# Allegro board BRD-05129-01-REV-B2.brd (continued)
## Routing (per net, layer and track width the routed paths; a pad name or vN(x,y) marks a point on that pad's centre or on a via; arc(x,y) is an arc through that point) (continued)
GND1_RS485: length 2.3
  TOP w0.381: C602.2 116.23,94.62 v1(116.55,94.29) U95.6
  vias: v1(110.62,93.41) v1(110.62,92.26) v1(110.62,91.12)
GND2_RS485:
  vias: v1(110.66,84.12) v1(110.66,82.98) v1(110.66,81.83)
VCC_BATT: length 3.2
  TOP w0.305: JA1.A1 v4(16.83,41.77)
  BOTTOM w0.381: v4(16.83,41.77) 17.02,41.96 C621.1 R44.1
VCCOEN_PL_M2C: length 235.8
  TOP w0.305: JA1.A20 v4(16,53.26)
  L03_SIG w0.254: v1(70.7,15.88) 69.26,17.31 69.26,18.61 70.43,19.78 v1(70.43,21.42)
  L05_SIG w0.254: v1(39.4,36.65) 39.4,36.21 46.15,29.46 51.23,29.46 53.56,27.12 53.56,25.83 54.5,24.89 54.5,24.13 55.33,23.3 58.96,23.3 59.23,23.03 61.99,23.03 62,23.05 65.04,23.05 66.67,21.41 66.67,19.9 v1(70.7,15.88) ; v1(67.22,24.85) 67.22,22.56 68.37,21.41 70.42,21.41 v1(70.43,21.42)
  L10_SIG w0.254: v1(123.1,67.88) 123.74,68.52 123.74,69.18 121.71,71.22 109.32,71.22 107.41,73.12 95.4,73.12 93.7,74.82 79.47,74.82 78.91,75.38 66.88,75.38 64.92,73.43 60.92,73.43 60.49,73.86 57.72,73.86 57.58,73.72 56.8,73.72 56.25,74.26 45.21,74.26 44.6,74.87 38.34,74.87 36.39,76.82 36.39,81.1 35.38,82.11 34.37,82.11 v1(33.77,81.52) 29.28,81.52 27.23,79.47 27.23,62.28 v1(21.64,56.69) ; v4(16,53.26) 16.46,53.72 21.51,53.72 25.1,50.13 28.17,50.13 32.53,45.77 36.8,45.77 39,43.57 39,41.79 39.4,41.39 v1(39.4,36.65)
  BOTTOM w0.178: v1(33.77,81.52) 34.3,82.05 U3.9 ; v1(67.22,24.85) 67.22,25.27 67.35,25.4 U97.9
  BOTTOM w0.254: Q26.1 v1(70.43,21.42) ; Q27.1 v1(123.1,67.88) ; U122.5 v1(70.7,15.88)
  BOTTOM w0.381: v4(16,53.26) 16.53,53.79 20.19,53.79 21.64,55.24 v1(21.64,56.69)
VCCOEN_PS_M2C: length 61.2
  TOP w0.305: JA1.A19 v4(16.83,53.2)
  L12_SIG w0.254: v4(16.83,53.2) 16.09,53.93 12.35,53.93 12.04,54.24 10.49,54.24 10.21,53.96 9.06,53.96 8.47,53.37 6.54,53.37 v1(5.25,54.66) 5.25,56.05 6.19,56.99 8.25,56.99 8.72,57.46 9.81,57.46 10.33,57.98 10.33,63.34 10.94,63.95 10.94,78.51 14.04,81.61 24.41,81.61 24.61,81.4 v1(27.29,81.4)
  BOTTOM w0.178: v1(27.29,81.4) 26.76,81.93 U5.9
  BOTTOM w0.203: v1(5.25,54.66) 5.53,54.38 U1.12
A_RS485: length 16.3
  TOP w0.381: v1(128.51,85.64) D22.1 126.14,85.64 124.87,84.38 123.17,84.38 122.9,84.11 U95.20
  BOTTOM w0.381: D22.1 v1(128.51,85.64) 130.48,85.64 132.63,87.8 J22.1
B_RS485: length 29.5
  TOP w0.381: J21.1 131.49,86.53 130.48,87.54 D22.2 124.1,87.54 122.58,86.03 122.58,85.33 121.63,84.39 U95.19
  BOTTOM w0.381: J22.2 134.67,93.69 134.67,87.04 J21.1
BRK_CTL_CONN: length 33
  TOP w0.381: 113.45,7.15 J46.1 ; J46.1 116.87,8.86 ; J46.1 116.87,7.15 ; J46.1 115.16,5.45 ; J46.1 116.87,5.45 ; J46.1 113.45,8.86 ; J46.1 113.45,5.45 ; J46.1 115.16,8.86
  BOTTOM w0.381: J46.1 116.87,7.15 ; J46.1 113.45,7.15 ; J46.1 115.16,5.45 ; J46.1 113.45,8.86 ; J46.1 116.87,5.45 ; J46.1 115.16,8.86 ; J46.1 116.87,8.86 ; J46.1 113.45,5.45
  vias: v1(113.31,11.5) v1(113.31,10.23) v1(114.58,11.5) v1(114.58,10.23) v1(115.85,11.5) v1(115.85,10.23) v1(117.12,11.5) v1(117.12,10.23)
BRK_GATE: length 2.7
  TOP w0.127: Q42.4 109.93,13.03 109.66,12.76 R678.2
BRK_GATE_S: length 2.3
  TOP w0.127: U121.5 R679.1 R678.1
CAN_CANH: length 16.8
  TOP w0.127: U94.B13 111.04,104.54 v1(110.83,104.75) ; v1(114.69,106.08) U94.A13
  L03_SIG w0.102: v1(110.83,104.75) 112.16,106.08 v1(114.69,106.08) 115.48,105.29 J20.1 117.16,105.37 J18.2
CAN_CANL: length 19.4
  TOP w0.127: v1(114.69,104.81) U94.A12 113.37,104.31 113.15,104.09 111.87,104.09 U94.B12
  L03_SIG w0.102: v1(114.69,104.81) 115.41,104.1 117.68,104.1 119.41,105.83 120.4,105.83 120.93,105.29 J19.1 122.16,105.3 J18.1
CAN_EN: length 7.9
  TOP w0.127: U94.A6 v1(106.11,101) ; U94.B6 109.66,102.54 v1(110.05,102.14)
  L03_SIG w0.102: v1(106.11,101) 107.93,101 109.08,102.14 v1(110.05,102.14)
  BOTTOM w0.13: R516.2 v1(106.11,101)
CAN_INH: length 6.7
  TOP w0.127: U94.B7 109.42,102.04 109.77,101.69 109.77,100.97 108.53,99.73 U94.A7 v1(106.11,99.73)
  BOTTOM w0.13: R514.1 v1(106.11,99.73)
CAN_STB_B: length 5.9
  TOP w0.127: U94.B14 111.82,107.08 112.08,107.35 U94.A14 v1(114.69,107.35)
  BOTTOM w0.13: R515.2 114.69,107.36 v1(114.69,107.35)
CC_PL_PGOOD: length 297.6
  TOP w0.254: v1(65.93,10.92) 69.51,10.92 v1(75.18,16.58)
  L03_SIG w0.254: v1(65.93,10.92) 63.8,10.92 63.47,10.59 61.24,10.59 59.84,11.98 48.72,11.98 48.26,12.45 45.6,12.45 44.88,11.73 38.65,11.73 34.53,15.86 19.54,15.86 19.42,15.98 15.35,15.98 14.78,15.41 11.73,15.41 v1(10.97,16.18) ; v1(75.44,88.46) 74.46,89.44 73.5,89.44 73.3,89.24 72.37,89.24 71.8,88.67 68.32,88.67 67.79,89.2 66.57,89.2 66.14,88.77 62.12,88.77 61.41,89.48 59.14,89.48 58.81,89.81 57.43,89.81 56.31,88.69 55.5,88.69 53.74,90.45 51.53,90.45 51.1,90.88 45.97,90.88 40.41,85.31 37.79,85.31 34.82,82.34 v1(34.82,81.45) ; v1(67.83,24.25) 68.1,24.52 68.94,24.52 70.61,22.86 71.17,22.86 72.01,22.02 72.01,21.18 74.32,18.87 74.32,17.44 v1(75.18,16.58)
  L05_SIG w0.254: v1(53.92,30.2) 51.89,32.23 51.89,35.02 49.02,37.89 44.76,37.89 40.13,42.52 40.13,43.05 39.59,43.59 37.5,43.59 37.12,43.97 v1(36.22,43.97) ; v1(116.66,26.23) 113.94,23.52 107.08,23.52 105.81,24.79 85.47,24.79 81.02,20.34 78.66,20.34 77.72,19.4 77.72,17.5 76.8,16.58 v1(75.18,16.58)
  L10_SIG w0.254: v1(67.83,24.25) 67.83,25.85 66.82,26.86 64.32,26.86 61.63,29.54 58.8,29.54 v1(57.79,28.53) 55.58,28.53 v1(53.92,30.2) ; v1(40.43,59.53) 40.43,63.14 34.13,69.44 34.13,80.36 34.82,81.05 v1(34.82,81.45)
  L12_SIG w0.254: v1(36.22,43.97) 36.99,43.97 37.59,44.57 37.59,53.56 39.58,55.55 39.58,58.68 v1(40.43,59.53)
  BOTTOM w0.13: R28.2 v1(36.22,43.97) 36.01,43.76 U19.25 ; Q10.1 10.36,16.78 v1(10.97,16.18)
  BOTTOM w0.178: U3.8 34.99,81.62 v1(34.82,81.45) ; Q43.1 113.56,39.29 ; U97.8 68.41,24.54 68.11,24.25 v1(67.83,24.25)
  BOTTOM w0.254: U122.3 74.97,16.38 v1(75.18,16.58) ; v1(75.44,88.46) 75.65,88.26 U8.3 ; v1(116.66,26.23) 118.18,26.23 121.31,29.36 121.31,33.06 119.8,34.56 118.59,34.56 116.21,36.95 115.55,36.95 113.56,38.94 113.56,39.29 ; U9.3 58,28.74 v1(57.79,28.53)
CC_PS_PGOOD: length 183.1
  TOP w0.254: v1(29.61,43.94) 24.2,43.94 v1(20.01,39.75)
  L03_SIG w0.254: v1(29.61,43.94) 30.64,44.97 32.81,44.97 34.02,43.76 35.07,43.76 36.14,44.83 v1(36.7,44.83)
  L05_SIG w0.254: v1(6.02,22.27) 7.51,23.77 7.51,35.05 11.17,38.71 11.17,43.56 10.17,44.56 10.17,47.53 9.29,48.41 8.51,48.41 7.46,49.45 7.46,51.51 v1(6.35,52.62)
  L10_SIG w0.254: v1(65.81,75.22) 64.66,74.06 61.18,74.06 60.7,74.54 58.34,74.54 v1(56.94,75.94)
  L12_SIG w0.254: v1(56.94,75.94) 56.94,76.44 55.5,77.88 53.5,77.88 53.21,77.59 53.21,76.55 52.96,76.3 51.71,76.3 50.72,77.29 46.45,77.29 46,76.83 46,75.92 44.98,74.9 42.24,74.9 41.76,75.37 34.42,75.37 v1(27.35,82.44) 26.71,83.09 14.31,83.09 10.31,79.09 10.31,67.25 6.22,63.17 6.22,58.11 4.62,56.51 4.62,54.35 v1(6.35,52.62) ; v1(6.02,22.27) 12.44,28.7 14.75,28.7 18.94,32.89 18.94,38.68 v1(20.01,39.75)
  BOTTOM w0.13: U19.24 35.49,44.1 36.22,44.83 v1(36.7,44.83) 36.82,44.95 R7.2 ; Q8.1 5.61,21.86 v1(6.02,22.27)
  BOTTOM w0.178: U5.8 27.18,82.61 v1(27.35,82.44)
  BOTTOM w0.203: U1.14 5.57,52.89 5.84,52.62 v1(6.35,52.62)
  BOTTOM w0.254: U12.3 65.61,75.01 v1(65.81,75.22) ; U96.3 56.69,75.69 v1(56.94,75.94)
CC_PS_POR_B: length 44.1
  TOP w0.127: SW2.2 4.84,46.98 5.14,47.28 v1(9.56,47.28)
  L12_SIG w0.102: v1(9.56,47.28) 11.22,45.61 11.22,41.46 13.75,38.93 15.97,38.93 19.6,42.56 19.6,43.4 24.74,48.54 32.29,48.54 33.21,47.62 v1(35.07,47.62)
  BOTTOM w0.13: R452.1 35.08,47.61 v1(35.07,47.62)
CC_PS_POR_B_R: length 2.9
  BOTTOM w0.13: U19.23 35.09,44.28 35.18,44.37 35.18,44.77 35.09,44.86 35.09,45.47 R452.2 C548.1
DC_LINK: length 117.9
  TOP w0.381: C751.1 94.69,23.33 ; C751.1 93.62,22.27 ; C751.1 93.62,21.2 ; C751.1 95.75,23.33 ; C751.1 94.69,21.2 ; C751.1 93.62,23.33 ; C751.1 95.75,22.27 ; C751.1 95.75,21.2 ; 125.16,5.45 J46.3 ; J46.3 126.42,8.41 ; J46.3 126.87,7.15 ; J46.3 123.9,8.41 ; J46.3 126.42,5.9 ; J46.3 125.16,8.86 ; J46.3 123.9,5.9 ; v1(110.98,25.29) 110.98,23.9 R659.2
  L03_SIG w0.381: J46.3 126.42,8.41 ; J46.3 126.42,5.9 ; J46.3 123.9,8.41 ; J46.3 126.87,7.15 ; J46.3 125.16,8.86 ; J46.3 125.16,5.45 ; J46.3 123.9,5.9 ; J46.3 123.45,7.15 ; 93.88,21.46 C751.1 ; C751.1 95.75,22.27 ; C751.1 93.62,22.27 ; C751.1 95.49,23.07 ; C751.1 94.69,21.2 ; C751.1 94.69,23.33 ; C751.1 93.88,23.07 ; C751.1 95.49,21.46
  L07_PWR w0.381: 94.69,21.07 C751.1 ; C751.1 95.58,21.37 ; C751.1 94.69,23.46 ; C751.1 93.79,23.16 ; C751.1 93.49,22.27 ; C751.1 95.88,22.27 ; C751.1 93.79,21.37 ; C751.1 95.58,23.16 ; 125.16,5.32 J46.3 ; J46.3 126.51,5.81 ; J46.3 126.51,8.5 ; J46.3 123.81,8.5 ; J46.3 123.32,7.15 ; J46.3 126.99,7.15 ; J46.3 125.16,8.99 ; J46.3 123.81,5.81
  BOTTOM w0.381: C751.1 95.75,23.33 ; C751.1 93.62,23.33 ; C751.1 93.62,22.27 ; C751.1 95.75,22.27 ; C751.1 94.69,21.2 ; C751.1 94.69,23.33 ; C751.1 93.62,21.2 ; C751.1 95.75,21.2 ; 123.9,8.41 J46.3 ; J46.3 126.42,8.41 ; J46.3 123.45,7.15 ; J46.3 126.87,7.15 ; J46.3 125.16,8.86 ; J46.3 126.42,5.9 ; J46.3 123.9,5.9 ; J46.3 125.16,5.45 ; R660.1 114.42,44.96 114.42,45.72 113.61,46.53 v1(106.09,46.53) ; R762.1 R761.1 111.23,31.99 ; v1(110.98,25.29) U113.1 ; R531.1 130.48,13.31 v1(130.27,13.1)
  vias: v1(95.93,27.86) v1(95.93,26.59) v1(97.2,27.86) v1(97.2,26.59) v1(97.71,62.53) v1(97.71,61.26) v1(97.71,59.99) v1(97.71,56.18) v1(97.71,49.83) v1(97.71,48.56) v1(97.71,46.02) v1(97.71,44.75) v1(97.71,43.48) v1(97.71,39.67) v1(97.71,34.59) v1(97.71,33.32) v1(97.71,32.05) v1(97.71,30.78) v1(97.71,29.51) v1(98.47,27.86) v1(98.47,26.59) v1(99.74,29.13) v1(99.74,27.86) v1(99.74,26.59) v1(101.01,29.13) v1(101.01,27.86) v1(101.01,26.59) v1(102.28,64.82) v1(102.28,63.55) v1(102.28,62.28) v1(102.28,47.8) v1(102.28,46.53) v1(102.28,45.26) v1(102.28,29.13) v1(102.28,27.86) v1(102.28,26.59) v1(103.55,64.82) v1(103.55,63.55) v1(103.55,62.28) v1(103.55,47.8) v1(103.55,46.53) v1(103.55,45.26) v1(103.55,29.13) v1(103.55,27.86) v1(103.55,26.59) v1(104.82,63.55) v1(104.82,62.28) v1(104.82,46.53) v1(104.82,45.26) v1(104.82,29.13) v1(104.82,27.86) v1(104.82,26.59) v1(106.09,64.82) v1(106.09,63.55) v1(106.09,62.28) v1(106.09,47.8) v1(106.09,45.26) v1(106.09,29.13) v1(106.09,27.86) v1(106.09,26.59) v1(107.36,27.86) v1(107.36,26.59) v1(108.63,27.86) v1(108.63,26.59) v1(114.25,31.34) v1(114.25,30.07) v1(129,16.91) v1(129,15.64) v1(129,14.37) v1(129,13.1) v1(129,11.83) v1(130.27,16.91) v1(130.27,15.64) v1(130.27,14.37) v1(130.27,11.83)
DCLINK_CONN: length 46.5
  TOP w0.635: J39.1 127.83,21.85 ; J39.1 123.01,26.67 ; J39.1 125.42,21.85 ; J39.1 125.42,26.67 ; J39.1 123.01,21.85 ; J39.1 123.01,24.26 ; J39.1 127.83,24.26 ; J39.1 127.83,26.67
  BOTTOM w0.635: J39.1 127.83,24.26 ; J39.1 125.42,26.67 ; J39.1 123.01,26.67 ; J39.1 123.01,21.85 ; J39.1 125.42,21.85 ; J39.1 123.01,24.26 ; J39.1 127.83,26.67 ; J39.1 127.83,21.85
  vias: v1(122.55,26.81) v1(122.55,25.54) v1(122.55,24.4) v1(122.55,23.26) v1(122.55,22.12) v1(122.55,20.85)
DCLINK_CRNT: length 42.5
  L12_SIG w0.381: v1(116.51,30.02) 116.51,33.03 115.29,34.26 110.99,34.26 110.36,34.9 107.36,34.9 105.36,36.9 97.94,36.9 90.6,44.24 86.22,44.24 84.88,45.58 v1(84.88,45.79)
  BOTTOM w0.381: R663.2 116.5,29.2 C759.1 v1(116.51,30.02) ; v1(84.88,45.79) R728.1
DCLINK_CS_B: length 9.7
  L12_SIG w0.102: v1(55.67,35.04) 54.78,35.92 v1(54.78,40.43)
  BOTTOM w0.13: v1(55.67,35.04) 56.94,35.04 57.18,34.79 U114.10 ; U115.7 53.56,41.11 54.11,41.11 v1(54.78,40.43)
DCLINK_CURRENT+: length 2.6
  TOP w0.381: C825.1 v1(64.88,33.65)
  BOTTOM w0.254: v1(64.88,33.65) 64.39,34.14 U114.8
  BOTTOM w0.381: C825.1 v1(64.88,33.65)
DCLINK_CURRENT-: length 2.4
  TOP w0.381: C824.1 v1(64.88,34.79)
  BOTTOM w0.254: U114.7 v1(64.88,34.79)
  BOTTOM w0.381: C824.1 v1(64.88,34.79)
DCLINK_DATAA: length 7
  BOTTOM w0.13: U114.14 55.16,37.39 54.15,38.4 54.15,40.43 53.89,40.7 U115.8
DCLINK_DATAB: length 9.9
  L12_SIG w0.102: v1(53.47,39.67) 53.47,40.44 54.07,41.04 55.13,41.04 55.56,40.61 55.56,37.96 v1(56.78,36.74)
  BOTTOM w0.13: U114.13 v1(56.78,36.74) ; v1(53.47,39.67) 52.97,40.18 U115.9
DCLINK_INPUT: length 3.4
  TOP w0.381: R659.1 113.58,23.71 v1(113.58,25.29)
  BOTTOM w0.381: v1(113.58,25.29) U113.8
  vias: v1(113.36,19.58) v1(113.36,18.44) v1(114.5,19.58) v1(114.5,18.44) v1(115.9,19.58) v1(115.9,18.44) v1(117.04,18.44)
DCLINK_SCLK: length 7.4
  BOTTOM w0.13: U114.15 57.22,38.04 56.94,37.77 56.18,37.77 55.42,38.53 55.42,40.81 54.77,41.47 53.58,41.47 U115.6
DCLINK_VOCM: length 19.1
  L10_SIG w0.381: v1(69.96,39.33) v1(71.11,39.33) 71.17,39.39 74.89,39.39 v1(76.11,40.61) 77.19,41.69 81.45,41.69 81.81,42.06 82.6,42.06 v1(83.42,41.24)
  BOTTOM w0.254: v1(83.42,41.24) 83.48,41.3 U134.2 ; U133.2 76.24,40.74 v1(76.11,40.61)
  BOTTOM w0.381: U137.7 70.88,39.56 v1(71.11,39.33) ; U137.6 70.23,39.59 v1(69.96,39.33)
DCLINK_VOCM2: length 18
  L10_SIG w0.381: v1(84.88,41.38) 84.88,40.84 84.02,39.98 78.2,39.98 v1(77.64,40.53) 73.83,36.72 72.28,36.72 v1(72.26,36.7) 72.23,36.72 71.27,36.72 v1(71.24,36.7)
  BOTTOM w0.381: v1(84.88,41.38) R727.1 ; v1(77.64,40.53) R723.1
DCLINK_VOLT: length 53.9
  L10_SIG w0.381: v1(120.98,45.03) 119.53,43.58 117.85,43.58 116,41.73 116,40.31 114.98,39.29 100.5,39.29 97.53,42.26 92.58,42.26 90.59,44.26 86.19,44.26 85.67,44.78 82.85,44.78 82.6,45.02 v1(77.64,45.02)
  BOTTOM w0.381: v1(120.98,45.03) 120.66,44.72 120.66,43.03 120.37,42.74 U135.7 U135.6 ; v1(77.64,45.02) R724.1
DCLINK_VOLTAGE+: length 2.6
  TOP w0.381: C823.1 v1(64.88,39.19)
  BOTTOM w0.254: v1(64.88,39.19) 64.39,38.69 U114.1
  BOTTOM w0.381: C823.1 v1(64.88,39.19)
DCLINK_VOLTAGE-: length 2.4
  TOP w0.381: C822.1 v1(64.88,38.04)
  BOTTOM w0.254: U114.2 v1(64.88,38.04)
  BOTTOM w0.381: C822.1 v1(64.88,38.04)
EEPROM_WC_B: length 44.2
  TOP w0.127: v1(34.64,28.42) 34.5,28.28 R256.1
  L10_SIG w0.102: v1(63.8,18.52) 62.77,19.55 60.68,19.55 59.97,20.26 58.06,20.26 57.61,20.72 54.32,20.72 53.13,19.53 53.13,18.35 52.25,17.47 50.54,17.47 47.5,20.5 38.8,20.5 35.18,24.13 35.18,25.95 34.5,26.63 34.5,28.27 v1(34.64,28.42)
  BOTTOM w0.13: v1(34.64,28.42) 34.5,28.27 U15.7 ; v1(63.8,18.52) 63.8,21.23 Q19.3
FB_UTIL_3V3: length 3.4
  BOTTOM w0.254: U7.4 6.06,41.61 5.86,41.42 R38.1
  BOTTOM w0.457: R38.1 C41.2 R39.2
FTDI_3V3_FB: length 4.4
  BOTTOM w0.254: U11.4 39.78,15.72 39.72,15.79 38.99,15.79 38.79,15.59 R41.1
  BOTTOM w0.381: R41.1 38.05,15.59 R36.2 38.05,13.57 C44.2
FTDI_3V3_PG: length 3.3
  TOP w0.381: R40.2 41.19,16.44 40.47,15.72 39.93,15.72 v1(39.44,15.22)
  BOTTOM w0.229: U11.3 v1(39.44,15.22)
FTDI_EEPROM_WC: length 3.2
  BOTTOM w0.13: U24.52 62.29,19.96 62.29,19.96 R262.1 62.74,20.32 63.07,20.66 Q19.1
FTDI_LS_OE_B: length 5.3
  TOP w0.127: v1(53.1,16.46) 53.11,16.47 R235.2 53.75,17.43 Q13.1
  BOTTOM w0.13: U24.22 v1(53.1,16.46)
FTDI_PS_POR_B: length 41.9
  TOP w0.13: R266.2 v1(40.97,17.54)
  L03_SIG w0.102: v1(50.95,16.96) 49.7,18.21 49.7,20.75 48.32,22.13 48.32,25.59 47.11,26.79 47.11,27.55 43.71,30.96 40.07,30.96 39.69,31.33 38.72,31.33 38.34,30.95 35.35,30.95 33.78,29.38 v1(33.41,29.38)
  L10_SIG w0.102: v1(40.97,17.54) 41.59,16.92 46.1,16.92 46.26,17.07 47.42,17.07 47.54,16.96 v1(50.95,16.96)
  BOTTOM w0.13: Q46.1 40.93,17.58 v1(40.97,17.54) ; U24.23 v1(50.95,16.96)
FTDI_PS_SRST_B: length 30.6
  TOP w0.13: R765.2 v1(48.04,17.5)
  L03_SIG w0.102: v1(32.35,29.38) 32.83,28.9 33.98,28.9 35.11,30.03 37.1,30.03 37.12,30.01 40.35,30.01 40.79,30.45 43.43,30.45 46.4,27.48 46.4,22.27 48.64,20.04 48.64,18.1 v1(48.04,17.5)
  BOTTOM w0.13: U24.24 48.09,17.46 v1(48.04,17.5) 47.91,17.5 47.75,17.67 Q48.1
FTDI_TCK: length 22.7
  L03_SIG w0.102: v1(50.08,13.13) 48.26,14.95 47.84,14.95 45.87,16.92 45.87,17.72 45.39,18.21 43.51,18.21 40.18,21.54 40.18,23.16 39.38,23.96 v1(39.38,26.67)
  BOTTOM w0.13: U24.16 51.36,12.74 50.96,13.13 v1(50.08,13.13) ; U22.6 38.79,26.98 39.1,26.67 v1(39.38,26.67)
FTDI_TDI: length 21.5
  L03_SIG w0.102: v1(38.39,26.67) 38.39,24.04 37.61,23.26 37.61,21.73 38.71,20.64 39.9,20.64 43.35,17.19 44.24,17.19 v1(47.93,13.51)
  BOTTOM w0.13: v1(47.93,13.51) 48.38,13.96 U24.17 ; U22.7 v1(38.39,26.67)
FTDI_TDO: length 14.1
  TOP w0.13: U25.9 v1(47.31,24.75)
  L05_SIG w0.102: v1(50.88,14.46) 48.85,16.49 48.85,19.4 48.24,20 48.24,23.82 v1(47.31,24.75)
  BOTTOM w0.13: U24.18 v1(50.88,14.46)
FTDI_TMS: length 15.2
  TOP w0.13: U25.8 47.97,25.15 v1(47.31,25.81)
  L05_SIG w0.102: v1(47.31,25.81) 46.83,25.33 46.83,22.92 46.94,22.81 46.94,18.7 46.46,18.23 46.46,15.93 v1(47.93,14.47)
  BOTTOM w0.13: v1(47.93,14.47) 48.41,14.96 U24.19
FTDI_UARTB_RXD: length 11.8
  L10_SIG w0.102: v1(50.96,18.96) 46.13,23.79 46.13,25.33 v1(45.37,26.08)
  BOTTOM w0.13: U64.9 v1(45.37,26.08) ; U24.27 v1(50.96,18.96)
FTDI_UARTB_TXD: length 18
  L10_SIG w0.102: v1(45.37,27.14) 50.35,27.14 51.39,26.1 51.39,21.85 51.99,21.25 v1(51.99,18.46)
  BOTTOM w0.13: U64.8 44.71,26.48 v1(45.37,27.14) ; U24.26 v1(51.99,18.46)
FWUEN_C2M_B: length 27.4
  TOP w0.127: v1(2.97,76.12) 3.09,76.25 SW1.2
  TOP w0.13: C236.1 v1(2.97,76.12) ; JA1.C28 v4(14.29,58.91)
  L03_SIG w0.102: v1(2.97,76.12) 2.97,73.86 5.66,71.17 5.66,67.38 10.11,62.94 10.11,60.27 12.69,57.68 13.64,57.68 13.89,57.93 13.89,58.52 v4(14.29,58.91)
GEM0_AVDD_3V3: length 6.3
  TOP w0.254: U98.11 66.03,94.97 v1(67.02,95.96) ; v1(60.55,95.96) 61.53,94.98 U98.20
  TOP w0.381: C625.1 C635.1 61.1,96.5 v1(60.55,95.96)
  vias: v1(68.03,95.96) v1(69.05,95.96)
GEM1_AVDD_3V3: length 8.6
  BOTTOM w0.254: v1(93.2,89.98) 93.2,89.5 93.7,89 U99.11 ; v1(100.29,90.13) 100.29,89.88 99.87,89.45 99.11,89.45 98.94,89.29 U99.20
  BOTTOM w0.381: 107.17,89.28 C660.1 106.61,89.84 ; v1(93.2,89.98) 93.2,90.11 93.01,90.3 C659.1 C649.1 ; v1(100.29,90.13) 100.29,90.87 C658.1 C648.1
  vias: v1(106.09,89.45) v1(106.09,88.31) v1(106.09,87.17)
GEM1_XTAL_IN: length 21.7
  TOP w0.13: v1(80.95,79.21) 83.1,79.21 87.73,83.84 87.73,88.62 88.46,89.35 v1(88.46,89.4)
  BOTTOM w0.13: v1(88.46,89.4) 89.18,88.69 91.41,88.69 91.77,89.05 92.32,89.05 92.61,88.77 92.61,88.59 93.29,87.9 U99.9 ; R478.2 v1(80.95,79.21)
GEM1_XTAL_IN_R: length 1.9
  BOTTOM w0.13: U91.8 78.89,79.68 79.36,79.21 R478.1
GEM2_AVDD_3V3: length 7.4
  TOP w0.254: U101.11 98.94,89.6 v1(99.44,90.09) 99.36,90.17 C680.1 C681.1 ; U101.20 94.44,89.6 v1(94.06,89.98)
  TOP w0.381: 106.69,90.85 C682.1 ; C682.1 107.17,91.34 ; C682.1 107.17,90.37 ; v1(94.06,89.98) 94.06,90.62 C670.1 C671.1
  vias: v1(105.84,92.5) v1(105.84,91.49) v1(105.84,90.47)
GEM2_XTAL_IN: length 38.5
  TOP w0.127: v1(104.95,89.84) 104.23,89.11 101.91,89.11 101.57,89.45 101.03,89.45 100.19,88.61 100.19,88.09 100,87.9 U101.9
  L12_SIG w0.102: v1(104.95,89.84) 104.48,90.31 103.52,90.31 103,89.78 101.28,89.78 100.64,89.15 100.38,89.15 99.17,87.94 99.17,85.7 98.02,84.55 95.16,84.55 93.91,85.8 92.51,85.8 92.06,86.24 91.18,86.24 89.91,84.97 88.12,84.97 83.47,80.33 v1(80.95,80.33)
  BOTTOM w0.13: R480.2 v1(80.95,80.33)
GEM2_XTAL_IN_R: length 1.7
  BOTTOM w0.13: U91.7 77.71,80.33 R480.1
GISOIN_RS485: length 4
  TOP w0.381: D22.3 v1(126.07,86.59)
  BOTTOM w0.381: D23.3 v1(125.9,99.69) ; v1(114.68,85.28) 114.92,85.52 C604.2 ; C603.2 v1(114.67,86.52)
  vias: v1(110.38,80.23) v1(111.27,79.42)
GTR_DP0_C2M_N_NC: length 0.6
  TOP w0.089: v7(16.95,76.1) JA1.A56
GTR_DP0_C2M_P_NC: length 0.6
  TOP w0.089: v7(16.02,76.1) JA1.A55
GTR_DP0_M2C_N_NC: length 0.6
  TOP w0.089: v4(15.99,77.37) JA1.B58
GTR_DP0_M2C_P_NC: length 0.6
  TOP w0.089: v4(15.06,77.37) JA1.B57
GTR_DP1_C2M_N_NC: length 0.6
  TOP w0.089: JA1.C56 v7(14.41,76.1)
GTR_DP1_C2M_P_NC: length 0.6
  TOP w0.089: JA1.C55 v7(13.48,76.1)
GTR_DP1_M2C_N_NC: length 0.6
  TOP w0.089: JA1.A48 v3(16.95,71.02)
GTR_DP1_M2C_P_NC: length 0.6
  TOP w0.089: JA1.A47 v3(16.02,71.02)
GTR_DP2_C2M_C_N: length 3.6
  BOTTOM w0.109: U43.48 64.38,87.34 64.46,87.26 64.46,85.96 64.95,85.46 64.95,85.13 C309.2
GTR_DP2_C2M_C_P: length 3.6
  BOTTOM w0.109: U43.47 64.78,87.41 64.71,87.33 64.71,86.06 65.2,85.57 65.2,85.21 C310.2
GTR_DP2_C2M_N: length 61
  TOP w0.089: JA1.B54 v3(15.99,74.83)
  L03_SIG w0.109: v1(64.68,82.12) 64.99,81.81 64.99,81.58 63.95,80.54 61.34,80.54 60.83,81.05 60.37,81.05 60.24,81.18 60.24,81.48 60.11,81.6 59.93,81.6 59.79,81.47 59.79,81.18 59.66,81.05 58.14,81.05 57.78,80.69 53.54,80.69 52.78,79.93 44.78,79.93 44.5,80.21 44.5,80.87 42.77,82.6 38.07,82.6 37.08,81.61 37.08,80.27 31.13,74.32 15.78,74.32 15.62,74.48 15.62,74.7 15.75,74.83 v3(15.99,74.83)
  BOTTOM w0.109: v1(64.68,82.12) 64.99,82.43 64.99,83.63 C309.1
GTR_DP2_C2M_P: length 61
  TOP w0.089: JA1.B53 v3(15.06,74.83)
  L03_SIG w0.109: v1(65.55,82.12) 65.24,81.81 65.24,81.48 64.05,80.29 61.24,80.29 60.73,80.79 58.24,80.79 57.89,80.44 53.64,80.44 52.88,79.68 44.67,79.68 44.24,80.1 44.24,80.76 42.66,82.34 38.17,82.34 37.34,81.51 37.34,80.16 31.23,74.06 15.67,74.06 15.36,74.37 15.36,74.65 15.18,74.83 v3(15.06,74.83)
  BOTTOM w0.109: v1(65.55,82.12) 65.24,82.43 65.24,83.63 C310.1
GTR_DP2_M2C_C_N: length 3.4
  BOTTOM w0.109: U43.51 63.18,87.41 63.21,87.38 63.21,85.17 C315.2
GTR_DP2_M2C_C_P: length 3.4
  BOTTOM w0.109: U43.50 63.58,87.41 63.46,87.29 63.46,85.17 C316.2
GTR_DP2_M2C_N: length 60.6
  TOP w0.089: JA1.D58 v3(13.45,77.37)
  L03_SIG w0.109: v1(62.9,82.12) 63.21,81.81 63.21,81.62 63.1,81.5 62.03,81.5 61.45,82.08 61.45,82.27 61.66,82.48 61.66,82.66 61.53,82.79 61.34,82.79 61.13,82.58 60.95,82.58 60.6,82.93 53.74,82.93 51.76,80.95 45.82,80.95 43.26,83.51 37.23,83.51 35.61,81.89 35.61,81.19 31.32,76.91 13.21,76.91 13.08,77.04 13.08,77.24 13.21,77.37 v3(13.45,77.37)
  BOTTOM w0.109: C315.1 62.89,83.51 63.21,83.2 63.21,82.43 v1(62.9,82.12)
GTR_DP2_M2C_P: length 60.5
  TOP w0.109: JA1.D57 v3(12.52,77.37)
  L03_SIG w0.109: v3(12.52,77.37) 12.66,77.37 12.82,77.21 12.82,76.94 13.11,76.65 31.43,76.65 35.86,81.09 35.86,81.78 37.33,83.26 43.15,83.26 45.72,80.69 51.87,80.69 53.85,82.67 60.5,82.67 61.92,81.25 63.2,81.25 63.47,81.51 63.47,81.81 v1(63.77,82.12)
  BOTTOM w0.109: C316.1 63.78,83.51 63.46,83.2 63.46,82.43 v1(63.77,82.12)
GTR_DP3_C2M_N_NC: length 0.6
  TOP w0.089: JA1.D50 v3(13.45,72.29)
GTR_DP3_C2M_P_NC: length 0.6
  TOP w0.089: JA1.D49 v3(12.52,72.29)
GTR_DP3_M2C_N_NC: length 0.6
  TOP w0.109: JA1.C52 v3(14.41,73.56)
GTR_DP3_M2C_P_NC: length 0.6
  TOP w0.109: JA1.C51 v3(13.48,73.56)
GTR_REFCLK0_C2M_N_NC: length 0.6
  TOP w0.089: JA1.C48 v4(14.41,71.02)
GTR_REFCLK0_C2M_P_NC: length 0.6
  TOP w0.089: JA1.C47 v4(13.48,71.02)
GTR_REFCLK1_C2M_N_NC: length 0.6
  TOP w0.089: JA1.B50 v4(15.99,72.29)
GTR_REFCLK1_C2M_P_NC: length 0.6
  TOP w0.089: JA1.B49 v4(15.06,72.29)
GTR_REFCLK2_C2M_N: length 15.1
  TOP w0.089: v9(13.45,74.83) JA1.D54
  BOTTOM w0.089: v9(13.45,74.83) 13.1,74.49 13.1,74.25 12.86,74.01 11.63,74.01 10.03,72.41 10.03,67.44 9.25,66.66 8.28,66.66 R495.1 7.66,66.64 6.59,66.64 6.08,66.13 U89.5
GTR_REFCLK2_C2M_P: length 15.1
  TOP w0.089: v9(12.52,74.83) JA1.D53
  BOTTOM w0.089: v9(12.52,74.83) 12.85,74.51 12.85,74.36 12.75,74.27 11.53,74.27 11.28,74.01 11.1,74.01 11.02,74.09 10.87,74.09 10.77,73.99 10.77,73.84 10.86,73.75 10.86,73.6 9.78,72.51 9.78,67.55 9.15,66.92 8.28,66.92 R495.2 7.61,66.89 6.62,66.89 6.11,67.4 U89.4
GTR_REFCLK3_C2M_N_NC: length 0.6
  TOP w0.094: JA1.A52 v7(16.95,73.56)
GTR_REFCLK3_C2M_P_NC: length 0.6
  TOP w0.094: JA1.A51 v7(16.02,73.56)
HDA00_CC: length 90.9
  TOP w0.13: JA1.D16 v4(12.65,50.75)
  L05_SIG w0.102: v1(70.3,13.38) 70.3,13.97 69.16,15.11 67.82,15.11 65.62,17.3 65.62,18.69 64.53,19.78 59.56,19.78 58.9,20.44 56.38,20.44 54.09,22.74 53.3,22.74 52.55,23.49 52.55,26.46 50.62,28.39 45.68,28.39 39.48,34.59 37.59,34.59 v1(36.67,35.5)
  L10_SIG w0.102: v1(36.67,35.5) 37.16,35.99 37.16,38.78 35.96,39.98 33.32,39.98 31.53,41.76 28.69,41.76 24.3,46.15 24.3,48.33 20.09,52.55 17.99,52.55 17.44,51.99 13.33,51.99 13.09,51.75 13.09,51.2 v4(12.65,50.75)
  BOTTOM w0.13: J47.2 71.11,10.02 D21.1 R680.2 69.92,13 v1(70.3,13.38)
HDA01_NC: length 0.4
  TOP w0.13: JA1.D17 v4(12.65,51.38)
HDA02: length 123.3
  TOP w0.13: JA1.D18 v4(13.47,52.59)
  L05_SIG w0.102: v4(13.47,52.59) 13.89,53.01 13.89,53.51 14.1,53.73 17.35,53.73 18.25,52.83 33.36,52.83 34.11,52.08 41,52.08 42.02,51.06 45.76,51.06 46.04,51.34 48.44,51.34 50.74,53.63 52.06,53.63 53.97,55.54 53.97,64.29 54.74,65.06 64.96,65.06 66.08,63.94 66.08,59.67 65.88,59.48 65.88,56.06 67,54.94 67.66,54.94 68.05,54.55 74.16,54.55 74.54,54.93 77.65,54.93 78.02,54.55 81.43,54.55 82.12,53.86 85.46,53.86 85.7,54.1 87.42,54.1 89.73,51.79 93.04,51.79 97.13,47.7 99.51,47.7 101.37,45.84 106.42,45.84 106.85,45.41 v1(106.85,43.17)
  BOTTOM w0.13: R618.1 v1(106.85,43.17)
HDA03: length 121.8
  TOP w0.13: JA1.B16 v4(15.19,50.75)
  L05_SIG w0.102: v1(106.85,60.06) 106.85,60.63 107.34,61.11 107.34,65.43 106.55,66.21 98.57,66.21 97.48,65.12 90.34,65.12 87.6,67.86 87.04,67.86 84.86,70.05 77.87,70.05 77.62,69.79 74.62,69.79 69.31,64.49 68.67,64.49 67.76,65.4 65.29,65.4 65.15,65.53 54.34,65.53 53.49,64.69 53.49,56.77 51.1,54.38 50.14,54.38 48.64,52.88 43.28,52.88 42.95,52.55 34.54,52.55 33.55,53.54 18.21,53.54 17.7,54.05 13.51,54.05 13.05,53.59 13.05,52.19 13.33,51.91 14.5,51.91 14.75,51.66 14.75,51.18 v4(15.19,50.75)
  BOTTOM w0.13: R627.1 v1(106.85,60.06)
HDA04: length 115
  TOP w0.13: JA1.B17 v4(15.19,51.38)
  L12_SIG w0.102: v4(15.19,51.38) 15.62,50.95 15.62,50.38 15.78,50.21 17.98,50.21 38.47,70.71 42.27,70.71 43.04,71.48 46.26,71.48 47.72,72.95 50.44,72.95 50.72,73.22 57.45,73.22 57.52,73.29 63.46,73.29 65.02,74.85 65.02,76.37 65.81,77.16 66.21,77.16 67.79,78.74 83.9,78.74 88.18,83.02 91.25,83.02 92.11,83.88 94.22,83.88 94.69,83.41 98.49,83.41 99.13,84.05 100.94,84.05 101.33,84.43 102.65,84.43 103.12,83.97 103.12,78.48 103.67,77.93 105.36,77.93 v1(106.35,76.95)
  BOTTOM w0.13: R633.1 v1(106.35,76.95)
HDA05: length 122.5
  TOP w0.13: JA1.B18 v4(16.01,52.59)
  L05_SIG w0.102: v1(106.85,38.15) 105.26,39.74 103.03,39.74 101.09,41.68 101.09,42.52 99.62,43.99 97.33,43.99 95.42,45.89 95.42,46.71 91.03,51.1 88.31,51.1 87.8,51.61 85.77,51.61 85.26,52.12 78.15,52.12 77.9,51.86 71.17,51.86 70.4,52.62 68.34,52.62 65.41,55.55 65.41,59.67 65.6,59.87 65.6,60.52 65.6,60.53 65.6,63.75 64.76,64.58 55.04,64.58 54.44,63.99 54.44,54.01 50.95,50.52 47.27,50.52 46.83,50.08 42.01,50.08 41.22,50.87 33.35,50.87 32.43,51.79 16.81,51.79 v4(16.01,52.59)
  BOTTOM w0.13: v1(106.85,38.15) 106.85,38.41 R620.1
HDA06: length 165.4
  TOP w0.13: U116.11 v1(120.42,71.94) ; JA1.C18 v4(14.29,52.56)
  L03_SIG w0.102: v1(120.42,71.94) 122.32,73.83 124.89,73.83 126.92,75.87 126.92,89.96 126.28,90.6 126.28,93.57 v1(125.62,94.23)
  L12_SIG w0.102: v4(14.29,52.56) 14.91,51.94 17.83,51.94 22.27,56.38 22.27,57.41 36.94,72.08 38.84,72.08 39.8,73.04 44.67,73.04 45.71,74.09 49.97,74.09 50.31,74.43 55.71,74.43 56.21,74.93 58.76,74.93 60.02,76.18 60.02,78.36 60.9,79.24 60.9,80.07 61.47,80.64 71.99,80.64 73.45,82.1 84.56,82.1 88.83,86.37 90.15,86.37 91.34,87.55 92.12,87.55 92.74,86.93 94.49,86.93 95.41,87.85 97.88,87.85 99.65,89.62 100.44,89.62 101.08,90.25 102.8,90.25 103.87,91.32 104.76,91.32 105.06,91.02 106.03,91.02 106.68,90.37 109.37,90.37 109.72,90.01 114.22,90.01 114.4,90.19 118.54,90.19 119.07,90.72 125.06,90.72 126.26,91.92 126.26,93.59 v1(125.62,94.23)
  BOTTOM w0.13: U117.11 125.32,94.53 v1(125.62,94.23)
HDA07: length 159.7
  TOP w0.13: JA1.C19 v4(14.29,53.2) ; U116.10 120.93,72.59 v1(120.44,73.07)
  L03_SIG w0.102: v1(120.44,73.07) 120.44,73.28 124.23,77.07 124.23,82.06 124.94,82.77 124.94,91.58 v1(125.66,92.3)
  L12_SIG w0.102: v1(125.66,92.3) 113.42,92.3 111.65,94.07 105.77,94.07 103.09,91.38 100.93,91.38 100.29,90.74 99.41,90.74 97.03,88.37 94.85,88.37 94.26,87.78 92.56,87.78 92.32,88.03 90.58,88.03 90.07,87.51 88.97,87.51 88.58,87.12 88.58,86.8 84.36,82.58 73.06,82.58 71.6,81.12 61,81.12 59.36,79.47 59.36,76.53 58.24,75.41 55.93,75.41 55.44,74.93 52.29,74.93 50.92,76.3 49.83,76.3 48.61,75.08 45.95,75.08 45.21,74.34 41.92,74.34 41.45,74.81 37.6,74.81 20.21,57.43 20.21,55.01 17.4,52.19 15.01,52.19 14.75,52.45 14.75,52.73 v4(14.29,53.2)
  BOTTOM w0.13: v1(125.66,92.3) 125.35,91.99 124.44,91.99
HDA08_CC: length 70.1
  TOP w0.13: JA1.C20 v4(13.46,53.26)
  L12_SIG w0.102: v4(13.46,53.26) 13.08,52.88 13.08,52.32 12.75,52 11.83,52 11.57,51.74 6.37,51.74 4.03,54.07 4.03,57.12 4.85,57.93 4.85,64.28 6.6,66.04 6.6,71.16 7.77,72.33 7.77,74.42 6.45,75.74 6.45,76.27 4.44,78.28 4.44,79.42 2.56,81.3 2.56,82.57 1.6,83.54 1.6,88.9 2.33,89.63 2.33,93.65 1.88,94.1 1.88,100.76 2.79,101.67 2.79,104.62 v6(2.21,105.2)
  BOTTOM w0.13: Q20.1 2.33,106.62 2.23,106.52 R261.1 2.21,106.05 v6(2.21,105.2)
HDA09_NC: length 0.4
  TOP w0.13: JA1.A15 v4(16.83,50.66)
HDA10: length 149
  TOP w0.13: v1(120.16,70.53) 120.27,70.64 U116.13 ; JA1.A16 v4(16.83,51.29)
  L12_SIG w0.102: v4(16.83,51.29) 18.03,51.29 38.18,71.44 41.1,71.44 42.1,72.45 45.14,72.45 46.22,73.52 50.21,73.52 50.48,73.79 57.22,73.79 57.29,73.86 60.31,73.86 62.12,75.67 62.12,76.96 62.81,77.64 63.72,77.64 65.63,79.55 74.29,79.55 74.5,79.76 84.11,79.76 88.39,84.03 89.92,84.03 91.09,85.2 93.7,85.2 94.93,83.98 98.25,83.98 100,85.72 100,87.96 100.61,88.58 100.88,88.58 101.51,89.21 103.44,89.21 103.73,88.92 109.8,88.92 110.84,87.88 117.34,87.88 119.35,89.88 v1(120.56,89.88) 120.56,88.93 119.55,87.93 119.55,83.36 120.53,82.38 120.53,81.69 121.59,80.63 121.59,71.95 v1(120.16,70.53)
  BOTTOM w0.13: v1(120.56,89.88) 120.56,90.3 120.13,90.72 U117.3
HDA11: length 7.1
  TOP w0.13: JA1.A17 v4(16,51.36)
  BOTTOM w0.13: R276.1 12.49,50.08 12.62,50.21 14.1,50.21 14.47,50.21 14.74,50.48 14.74,51.57 15,51.83 15.53,51.83 v4(16,51.36)
HDA12: length 2.5
  TOP w0.13: JA1.D20 v4(12.65,53.29)
  BOTTOM w0.13: v4(12.65,53.29) 11.95,52.59 11.38,52.59 11.04,52.25 R278.1
HDA13: length 3.8
  TOP w0.13: JA1.D21 v4(13.47,54.49)
  BOTTOM w0.13: R280.1 11.74,54.85 11.74,54.7 12.33,54.11 13.09,54.11 v4(13.47,54.49)
HDA14: length 3.4
  TOP w0.13: JA1.D22 v4(12.65,54.56)
  BOTTOM w0.13: R282.1 11.5,56.35 11.5,56.14 12.17,55.47 12.17,55.04 v4(12.65,54.56)
HDA15: length 5.7
  TOP w0.13: JA1.B20 v4(15.19,53.29)
  BOTTOM w0.13: v4(15.19,53.29) 14.73,52.84 14.73,52.38 14.22,51.86 12.11,51.86 11.48,51.23 R277.1
HDA16_CC: length 6
  TOP w0.13: JA1.B21 v4(16.01,54.49)
  L10_SIG w0.102: v4(16.01,54.49) 15.26,53.74 12.49,53.74 12.39,53.65 12.12,53.65 v1(11.86,53.39)
  BOTTOM w0.13: R279.1 v1(11.86,53.39)
HDA17: length 5.2
  TOP w0.13: JA1.B22 v4(15.19,54.56)
  BOTTOM w0.13: v4(15.19,54.56) 14.39,53.77 12.16,53.77 11.81,54.12 11.45,54.12 R281.1
HDA18: length 5.4
  TOP w0.13: JA1.C22 v4(14.29,55.1)
  BOTTOM w0.13: v4(14.29,55.1) 13.59,55.8 12.45,55.8 11.93,56.31 11.93,57.19 R283.1
HDA19_NC: length 0.6
  TOP w0.13: JA1.C23 v4(13.46,55.17)
HDA20: length 141.7
  TOP w0.13: U121.6 108.07,13.79 108.3,13.56 v1(108.91,13.56) ; JA1.C24 v4(14.29,56.37)
  L05_SIG w0.102: v1(108.91,13.56) 105.38,10.03 79.77,10.03 74.32,15.49 74.32,20.9 71.37,23.85 71.37,24.91 70.91,25.37 64.97,25.37 63.46,23.86 55.46,23.86 54.92,24.4 54.92,25.26 54.2,25.98 54.2,27.2 53.92,27.48 53.92,28.75 54.45,29.28 54.45,30.68 52.89,32.24 52.89,40.61 50.61,42.9 47.82,42.9 40.33,50.39 33.4,50.39 32.99,49.98 v1(18.51,49.98)
  L10_SIG w0.102: v1(18.51,49.98) 18.51,49.14 17.7,48.33 14.91,48.33 14.32,48.92 14.32,49.88 13.99,50.21 11.98,50.21 11.35,50.85 11.35,53.61 11.86,54.12 12.92,54.12 13.05,54.25 13.05,55.47 13.46,55.88 13.79,55.88 v4(14.29,56.37)
HDA21: length 26.1
  TOP w0.13: JA3.C10 v4(44.35,62.79) ; v1(59.61,72.82) 59.61,72.79 58.49,71.67 R579.2
  L10_SIG w0.102: v1(59.61,72.82) 58.72,71.93 58.72,71.12 56.41,68.8 48.94,68.8 44.35,64.21 v4(44.35,62.79)
  BOTTOM w0.13: v1(59.61,72.82) 59.61,72.21 59.09,71.69 U100.6
HDA22: length 33.6
  TOP w0.13: R580.2 57.88,72.68 58.65,73.45 59.9,73.45 60.3,73.05 60.3,72.39 v1(61.03,71.65) ; JA3.A10 v4(46.89,62.79)
  L05_SIG w0.102: v1(61.03,71.65) 59.84,71.65 59.22,72.27 57.39,72.27 56.51,73.15 52.91,73.15 50.49,70.73 49.72,70.73 46.91,67.93 46.91,67.18 45.46,65.73 45.46,65.7 45.35,65.59 45.35,63.82 45.99,63.18 46.27,63.18 46.67,62.79 v4(46.89,62.79)
  BOTTOM w0.13: U100.5 58.39,72.34 59.38,73.32 60.1,73.32 60.33,73.09 60.33,72.36 v1(61.03,71.65)
HPA00_CCN: length 62.6
  TOP w0.094: JA1.C4 v3(14.34,43.67)
  L03_SIG w0.102: v3(14.34,43.67) 14.34,44.07 14.05,44.36 13.15,44.36 12.94,44.57 12.16,44.57 11.38,43.79 11.38,37.38 12.42,36.34 27.23,36.34 28.06,37.18 38.17,37.18 40.89,39.9 40.89,40.25 v1(42.13,41.5)
  BOTTOM w0.13: U109.13 46.49,52.15 45.23,53.41 43.05,53.41 42.49,52.85 42.49,41.85 v1(42.13,41.5)
HPA00_CCP_CLK: length 55.6
  TOP w0.094: JA1.C3 v4(14.34,43.04)
  L03_SIG w0.102: v4(14.34,43.04) 13.96,42.66 13.33,42.66 13.04,42.37 13.04,41.03 12.65,40.64 12.65,39.02 13.77,37.9 23.67,37.9 25.38,39.61 30.66,39.61 31.47,40.41 37.36,40.41 39.29,42.35 40.24,42.35 v1(40.79,42.9)
  BOTTOM w0.13: v1(40.79,42.9) 40.79,53.26 42.2,54.67 45.53,54.67 47.26,52.95 47.88,52.95 47.89,52.95 U109.15
HPA01N: length 44.8
  TOP w0.089: JA1.D8 v3(12.55,45.64)
  L03_SIG w0.102: v1(43.85,52.32) 43.85,52.84 43.54,53.15 37.13,53.15 36.54,52.56 29.6,52.56 28.11,51.07 25.62,51.07 19.1,44.55 13.35,44.55 13.08,44.82 13.08,45.12 v3(12.55,45.64)
  BOTTOM w0.13: v1(43.85,52.32) 43.85,50.3 47.26,46.88 47.88,46.88 47.89,46.89 U111.15
HPA01P: length 76.3
  TOP w0.094: JA1.D7 v3(12.55,45.01)
  L03_SIG w0.102: v3(12.55,45.01) 12.45,45.01 12.4,45.06 11.99,45.06 11.04,44.1 11.04,37.87 8.96,35.78 8.96,31.32 11.2,29.08 14.29,29.08 18.64,33.42 20.82,35.61 34.97,35.61 35.43,36.06 37.77,36.06 41.58,39.87 42.85,39.87 v1(44.12,41.14)
  BOTTOM w0.13: v1(44.12,41.14) 43.07,42.19 43.07,52.55 43.46,52.93 44.85,52.93 46.48,51.3 48.69,51.3 49.11,51.73 U109.12
HPA02N: length 49.1
  TOP w0.094: JA1.D5 v3(12.55,43.74)
  L03_SIG w0.102: v1(45.39,46.45) 45.39,45.62 38.03,38.26 34.52,38.26 34.12,37.86 30.66,37.86 30.22,38.31 26.08,38.31 24.59,36.82 13.4,36.82 11.73,38.49 11.73,42.91 v3(12.55,43.74)
  BOTTOM w0.13: U111.13 47.77,46.09 47.24,45.56 46.27,45.56 v1(45.39,46.45)
HPA02P: length 47.4
  TOP w0.094: JA1.D4 v3(12.55,43.1)
  L03_SIG w0.102: v3(12.55,43.1) 12.1,42.65 12.1,38.76 13.56,37.3 24.51,37.3 25.95,38.74 30.59,38.74 30.92,38.41 33.75,38.41 34.68,39.34 38.43,39.34 44.17,45.08 44.17,46.43 44.79,47.04 46.27,47.04 v1(46.81,46.5)
  BOTTOM w0.13: U111.14 47.9,46.49 47.89,46.5 v1(46.81,46.5)
HPA03N: length 87.3
  TOP w0.089: JA1.C7 v3(14.38,45.61)
  L03_SIG w0.102: v1(45.09,40.14) 39.32,34.37 21.03,34.37 19.02,32.36 19.02,32.36 14.75,28.09 11.14,28.09 7.94,31.29 7.94,36.38 10.37,38.81 10.37,44.94 11.86,46.43 12.54,46.43 12.68,46.29 13.7,46.29 v3(14.38,45.61)
  BOTTOM w0.13: U109.14 47.9,52.55 47.89,52.56 46.67,52.56 45.34,53.89 42.8,53.89 41.63,52.73 41.63,40.76 42.25,40.14 v1(45.09,40.14)
HPA03P: length 69.3
  TOP w0.089: JA1.C6 v3(14.38,44.97)
  L03_SIG w0.102: v1(48.64,44.39) 47.11,42.87 46.73,42.87 38.71,34.85 20.81,34.85 14.55,28.6 11.11,28.6 8.48,31.23 8.48,36.3 10.7,38.52 10.7,44.6 12.17,46.07 13.61,46.07 13.97,45.71 13.97,45.38 v3(14.38,44.97)
  BOTTOM w0.13: v1(48.64,44.39) 49.11,44.87 U111.12
HPA04N: length 138
  TOP w0.094: JA1.B5 v4(15.09,43.74)
  TOP w0.127: Q31.1 80.66,94 R567.1 v1(81.45,93.9)
  TOP w0.13: v1(81.45,93.9) 81.45,93.01 78.58,90.14 78.58,80.34 75.26,77.01 v1(75.26,74.44)
  L03_SIG w0.102: v4(15.09,43.74) 15.54,43.3 15.54,42.85 14.55,41.86 14.55,41.49 13.69,40.62 13.69,39.55 14.27,38.96 21.36,38.96 30.37,47.97 31.93,47.97 33.34,49.37 36.9,49.37 37.57,50.04 46.71,50.04 53.06,56.39 53.06,65.56 54.25,66.75 66.9,66.75 71.95,71.8 71.95,72.71 73.68,74.44 v1(75.26,74.44)
  L05_SIG w0.102: v1(100.99,90.72) 100.23,91.48 99.16,91.48 98.62,92.03 95.88,92.03 94.8,93.11 91.23,93.11 90.44,93.9 v1(81.45,93.9)
  BOTTOM w0.13: U99.21 99.83,88.4 100.32,88.89 100.32,89.27 100.99,89.94 v1(100.99,90.72) R590.1 102.21,91.36 R576.2
HPA04P: length 139.1
  TOP w0.094: JA1.B4 v4(15.13,43.13)
  TOP w0.127: Q32.1 v1(106.12,85.36)
  L03_SIG w0.102: v1(106.12,85.36) 105.39,84.63 105.39,78.87 104.38,77.86 104.38,75.17 103.52,74.32 100.35,74.32 99.37,73.34 94.72,73.34 93.94,74.13 79.52,74.13 79.48,74.09 79.14,74.09 78.95,73.9 73.82,73.9 72.43,72.51 72.43,71.6 67.1,66.26 54.71,66.26 53.76,65.32 53.76,55.19 52.29,53.72 51.48,53.72 47,49.24 38.15,49.24 37.27,48.36 33.24,48.36 32.1,47.21 30.3,47.21 21.53,38.44 14.12,38.44 13.31,39.26 13.31,40.76 13.99,41.44 13.99,41.99 v4(15.13,43.13)
  BOTTOM w0.13: v1(106.12,85.36) 104.93,85.36 103.64,86.65 102.78,86.65 102.34,86.21 R589.1 102.21,86.28 R575.2 101.95,87.17 101.33,86.54 100.77,86.54 100.13,85.9 U99.26
HPA05_CCN: length 126.1
  TOP w0.094: JA1.B2 v4(15.13,41.82)
  L03_SIG w0.102: v4(15.13,41.82) 15.55,42.25 19.31,42.25 19.96,42.9 24.46,42.9 27.32,45.76 27.32,48.26 27.71,48.65 31.64,48.65 33.58,50.59 45.23,50.59 47.42,52.78 48.22,52.78 50.77,55.33 50.77,56.16 52.43,57.82 52.43,65.84 53.83,67.23 66.7,67.23 71.46,72 71.46,72.91 73.43,74.87 73.87,74.87 74.02,75.02 74.02,75.31 74.17,75.46 74.38,75.46 74.53,75.31 74.53,75.02 74.68,74.87 74.89,74.87 75.04,75.02 75.04,75.31 75.18,75.46 75.4,75.46 75.54,75.31 75.54,75.02 75.69,74.87 75.9,74.87 76.05,75.02 76.05,75.31 76.2,75.46 76.41,75.46 76.56,75.31 76.56,75.02 76.71,74.87 76.92,74.87 77.07,75.02 77.07,75.31 77.22,75.46 77.43,75.46 77.58,75.31 77.58,75.02 77.72,74.87 77.97,74.87 78.43,75.33 79.72,75.33 79.87,75.18 79.87,74.67 80.02,74.52 80.23,74.52 80.38,74.67 80.38,75.18 80.53,75.33 80.74,75.33 80.89,75.18 80.89,74.67 81.03,74.52 81.25,74.52 81.39,74.67 81.39,75.18 81.54,75.33 81.75,75.33 81.9,75.18 81.9,74.67 82.05,74.52 82.26,74.52 82.41,74.67 82.41,75.18 82.56,75.33 82.88,75.33 83,75.21 83,74.74 83.12,74.62 83.29,74.62 83.41,74.74 83.41,75.21 83.53,75.33 83.7,75.33 83.82,75.21 83.82,74.74 83.93,74.62 84.1,74.62 84.22,74.74 84.22,75.21 84.34,75.33 84.6,75.33 84.71,75.21 84.71,74.71 84.83,74.59 85,74.59 85.12,74.71 85.12,75.21 85.24,75.33 85.41,75.33 85.53,75.21 85.53,74.71 85.65,74.59 85.81,74.59 85.93,74.71 85.93,75.21 86.05,75.33 86.22,75.33 86.34,75.21 86.34,74.71 86.46,74.59 86.63,74.59 86.75,74.71 86.75,75.21 86.87,75.33 87.03,75.33 87.15,75.21 87.15,74.71 87.27,74.59 87.44,74.59 87.56,74.71 87.56,75.21 87.68,75.33 87.85,75.33 87.97,75.21 87.97,74.71 88.09,74.59 88.25,74.59 88.37,74.71 88.37,75.21 88.49,75.33 88.66,75.33 88.78,75.21 88.78,74.71 88.9,74.59 89.49,74.59 89.62,74.71 89.62,75.91 87.64,77.89 v1(87.64,79)
  BOTTOM w0.13: v1(87.64,79) 89.07,80.44 91.52,80.44 92.38,81.29 92.38,81.71 93.84,83.18 U99.1
HPA05_CCP: length 125.9
  TOP w0.094: JA1.B1 v4(15.13,41.18)
  L12_SIG w0.102: v4(15.13,41.18) 15.91,41.18 16.43,41.7 16.43,45.86 16.63,46.05 20.02,46.05 24.6,50.64 27.15,50.64 28.32,51.81 28.32,52.02 28.03,52.3 28.03,52.51 28.18,52.66 28.39,52.66 28.68,52.38 28.89,52.38 29.04,52.52 29.04,52.74 28.75,53.02 28.75,53.23 28.9,53.38 29.11,53.38 29.4,53.09 29.61,53.09 29.75,53.24 29.75,53.45 29.47,53.74 29.47,53.95 29.62,54.1 29.83,54.1 30.11,53.81 30.32,53.81 30.47,53.96 30.47,54.17 30.19,54.46 30.19,54.67 30.34,54.82 30.55,54.82 30.83,54.53 31.04,54.53 31.19,54.68 31.19,54.89 30.91,55.18 30.91,55.39 31.06,55.53 31.27,55.53 31.55,55.25 31.76,55.25 31.91,55.4 31.91,55.61 31.63,55.89 31.63,56.1 31.77,56.25 31.98,56.25 32.27,55.97 32.48,55.97 32.63,56.12 32.63,56.33 32.34,56.61 32.34,56.82 32.49,56.97 32.7,56.97 32.99,56.69 33.2,56.69 33.35,56.84 33.35,57.05 33.06,57.33 33.06,57.54 33.21,57.69 33.42,57.69 33.71,57.41 33.92,57.41 34.07,57.55 34.07,57.76 33.78,58.05 33.78,58.26 35.05,59.53 35.05,61.46 35.46,61.87 35.67,61.87 36.26,61.27 36.47,61.27 36.62,61.42 36.62,61.63 36.02,62.23 36.02,62.44 36.17,62.59 36.38,62.59 36.98,61.99 37.19,61.99 37.34,62.14 37.34,62.35 36.74,62.94 36.74,63.15 36.89,63.3 37.1,63.3 37.7,62.71 37.91,62.71 38.05,62.86 38.05,63.07 37.46,63.66 37.46,63.87 37.61,64.02 37.82,64.02 38.41,63.43 38.62,63.43 38.77,63.58 38.77,63.79 38.18,64.38 38.18,64.59 38.33,64.74 38.54,64.74 39.13,64.15 39.34,64.15 39.49,64.3 39.49,64.51 38.9,65.1 38.9,65.31 39.05,65.46 39.26,65.46 39.85,64.87 40.06,64.87 40.21,65.01 40.21,65.23 39.62,65.82 39.62,66.03 40.47,66.88 48.57,66.88 49.69,68 63.94,68 71.86,75.92 90.27,75.92 90.41,75.78 90.42,75.78 90.6,75.61 93.24,75.61 93.52,75.89 93.52,77.39 94.66,78.53 94.66,80.23 94.79,80.36 v1(94.79,81.68)
  BOTTOM w0.13: U99.39 94.94,82.6 94.79,82.44 v1(94.79,81.68)
HPA06N: length 127
  TOP w0.094: JA1.A4 v4(16.83,43.67)
  L03_SIG w0.102: v4(16.83,43.67) 19.1,43.67 21.42,46 21.63,46 22.21,45.42 22.42,45.42 22.57,45.56 22.57,45.77 21.99,46.35 21.99,46.57 23.08,47.66 23.29,47.66 23.69,47.26 23.9,47.26 24.05,47.41 24.05,47.62 23.65,48.02 23.65,48.23 23.8,48.38 24.01,48.38 24.41,47.98 24.62,47.98 24.77,48.13 24.77,48.34 24.37,48.74 24.37,48.95 24.52,49.1 24.73,49.1 25.13,48.7 25.34,48.7 25.49,48.85 25.49,49.06 25.09,49.46 25.09,49.67 25.76,50.34 28.2,50.34 29.94,52.08 30.74,52.08 30.89,51.93 30.89,51.55 31.04,51.41 31.25,51.41 31.4,51.55 31.4,51.93 31.55,52.08 31.76,52.08 31.91,51.93 31.91,51.55 32.05,51.41 32.26,51.41 32.41,51.55 32.41,51.93 32.56,52.08 36.39,52.08 36.5,51.96 37.36,51.96 37.51,52.11 37.51,52.48 37.66,52.63 37.87,52.63 38.01,52.48 38.01,52.11 38.16,51.96 38.37,51.96 38.52,52.11 38.52,52.48 38.67,52.63 38.88,52.63 39.03,52.48 39.03,52.11 39.18,51.96 39.39,51.96 39.54,52.11 39.54,52.48 39.69,52.63 39.9,52.63 40.05,52.48 40.05,52.11 40.2,51.96 40.41,51.96 40.55,52.11 40.55,52.48 40.7,52.63 40.91,52.63 41.06,52.48 41.06,52.11 41.21,51.96 41.42,51.96 41.57,52.11 41.57,52.48 41.72,52.63 41.93,52.63 42.08,52.48 42.08,52.11 42.23,51.96 42.44,51.96 42.59,52.11 42.59,52.48 42.74,52.63 42.95,52.63 43.09,52.48 43.09,52.11 43.45,51.76 44.34,51.76 46.96,54.38 46.96,55.22 48.21,56.46 49.48,56.46 51.3,58.28 51.3,66.18 53.31,68.19 66.3,68.19 66.89,68.79 66.89,69 66.66,69.23 66.66,69.44 66.81,69.59 67.02,69.59 67.25,69.36 67.46,69.36 67.61,69.51 67.61,69.72 67.38,69.95 67.38,70.16 67.53,70.31 67.74,70.31 67.97,70.08 68.18,70.08 68.33,70.23 68.33,70.44 68.1,70.67 68.1,70.88 68.25,71.03 68.46,71.03 68.69,70.8 68.9,70.8 69.05,70.95 69.05,71.16 68.82,71.39 68.82,71.6 68.97,71.75 69.18,71.75 69.41,71.52 69.62,71.52 69.77,71.67 69.77,71.88 69.54,72.11 69.54,72.32 69.69,72.46 69.9,72.46 70.13,72.23 70.34,72.23 70.5,72.4 70.5,73.31 73.61,76.41 77.4,76.41 77.55,76.56 77.55,76.91 77.7,77.05 77.91,77.05 78.06,76.91 78.06,76.56 78.2,76.41 78.42,76.41 78.56,76.56 78.56,76.91 78.71,77.05 78.92,77.05 79.07,76.91 79.07,76.56 79.22,76.41 79.43,76.41 79.58,76.56 79.58,76.91 79.73,77.05 79.94,77.05 80.09,76.91 80.09,76.56 80.24,76.41 80.45,76.41 80.6,76.56 80.6,76.91 80.74,77.05 80.96,77.05 81.1,76.91 81.1,76.56 81.25,76.41 81.46,76.41 81.61,76.56 81.61,76.91 81.76,77.05 81.97,77.05 82.12,76.91 82.12,76.56 82.27,76.41 82.48,76.41 82.63,76.56 82.63,76.91 82.78,77.05 84.2,77.05 84.35,77.2 84.35,77.9 84.5,78.05 84.71,78.05 84.86,77.9 84.86,77.2 85.01,77.05 85.51,77.05 85.75,77.29 85.75,79.19 v1(86.58,80.03)
  BOTTOM w0.13: v1(86.58,80.03) 88.52,81.96 90.85,81.96 91.87,82.98 91.87,83.74 92.16,84.03 92.58,84.03 93.45,84.9 U99.3
HPA06P: length 127
  TOP w0.094: JA1.A3 v4(17.02,42.89)
  L03_SIG w0.102: v4(17.02,42.89) 19,42.89 19.73,43.62 23.37,43.62 23.52,43.77 23.52,43.98 23.37,44.13 21.33,44.13 21.19,44.28 21.19,44.49 21.33,44.64 23.19,44.64 23.26,44.71 23.26,46.29 23.48,46.51 23.82,46.51 24.02,46.31 24.02,43.77 24.17,43.62 24.48,43.62 24.79,43.93 24.79,45.57 24.9,45.69 25.8,45.69 26.13,46.01 26.13,48.74 26.6,49.22 29.09,49.22 29.24,49.37 29.24,50.47 29.38,50.62 29.6,50.62 29.74,50.47 29.74,49.37 29.89,49.22 30.1,49.22 30.25,49.37 30.25,50.47 30.4,50.62 30.61,50.62 30.76,50.47 30.76,49.37 30.91,49.22 31.28,49.22 33.2,51.14 44.48,51.14 48.26,54.91 48.26,55.72 48.56,56.02 49.56,56.02 51.86,58.32 51.86,66.05 53.52,67.71 66.5,67.71 70.98,72.2 70.98,73.11 73.81,75.93 82.96,75.93 83.11,76.08 83.11,76.5 83.26,76.65 83.47,76.65 83.62,76.5 83.62,76.08 83.77,75.93 83.98,75.93 84.13,76.08 84.13,76.5 84.28,76.65 84.49,76.65 84.64,76.5 84.64,76.08 84.78,75.93 84.99,75.93 85.14,76.08 85.14,76.5 85.29,76.65 85.5,76.65 85.65,76.5 85.65,76.08 85.8,75.93 86.01,75.93 86.16,76.08 86.16,76.5 86.31,76.65 86.52,76.65 86.67,76.5 86.67,76.08 86.82,75.93 87.99,75.93 88.26,76.2 88.26,76.63 87.5,77.39 86.66,77.39 86.41,77.64 v1(86.41,79.02)
  BOTTOM w0.13: U99.2 93.42,84.4 93.17,84.15 93.17,83.19 92.57,82.6 91.99,82.6 90.34,80.95 88.34,80.95 v1(86.41,79.02)
HPA07N: length 128.6
  TOP w0.094: JA1.B8 v4(15.19,45.67)
  L12_SIG w0.102: v4(15.19,45.67) 14.74,46.11 14.74,47.77 14.98,48 19.38,48 21.49,50.11 21.49,51.39 22.64,52.53 22.85,52.53 23.37,52.01 23.58,52.01 23.73,52.16 23.73,52.37 23.21,52.89 23.21,53.1 23.35,53.25 23.56,53.25 24.09,52.73 24.3,52.73 24.44,52.88 24.44,53.09 23.92,53.61 23.92,53.82 24.07,53.97 24.28,53.97 24.8,53.45 25.01,53.45 25.16,53.6 25.16,53.81 24.64,54.33 24.64,54.54 24.79,54.69 25,54.69 25.52,54.17 25.73,54.17 25.88,54.32 25.88,54.53 25.36,55.05 25.36,55.26 25.51,55.41 25.72,55.41 26.24,54.89 26.45,54.89 26.6,55.03 26.6,55.24 26.08,55.77 26.08,55.98 26.23,56.12 26.44,56.12 26.96,55.6 27.17,55.6 27.32,55.75 27.32,55.96 26.8,56.48 26.8,56.69 26.95,56.84 27.16,56.84 27.68,56.32 27.89,56.32 28.04,56.47 28.04,56.68 27.52,57.2 27.52,57.41 27.88,57.78 29.66,57.78 40.43,68.54 46.71,68.54 48.65,70.49 54.32,70.49 54.7,70.1 58.29,70.1 58.55,69.83 62.85,69.83 65.42,72.41 66.11,72.41 71.05,77.35 77.42,77.35 77.59,77.17 90.38,77.17 91.16,77.95 92.02,77.95 92.48,78.41 92.48,79.55 93.7,80.77 93.7,81.53 94.44,82.27 95.17,82.27 95.64,81.8 95.64,76.87 94.65,75.88 v1(94.65,75.05)
  BOTTOM w0.13: v1(94.65,75.05) 94.65,75.57 95.66,76.58 95.66,82.26 95.94,82.55 U99.37
HPA07P_CLK: length 127.8
  TOP w0.094: JA1.B7 v4(15.19,45.03)
  L12_SIG w0.102: v4(15.19,45.03) 15.6,45.45 15.6,45.95 16.12,46.48 17.13,46.48 17.88,47.22 20.02,47.22 25.2,52.4 25.41,52.4 26.13,51.68 26.34,51.68 26.49,51.83 26.49,52.04 25.77,52.76 25.77,52.97 25.92,53.12 26.13,53.12 26.85,52.4 27.06,52.4 27.21,52.54 27.21,52.76 26.49,53.48 26.49,53.69 26.64,53.84 26.85,53.84 27.57,53.11 27.78,53.11 27.93,53.26 27.93,53.47 27.21,54.2 27.21,54.41 27.35,54.55 27.56,54.55 28.29,53.83 28.5,53.83 28.65,53.98 28.65,54.19 27.92,54.91 27.92,55.12 28.07,55.27 28.28,55.27 29,54.55 29.22,54.55 29.36,54.7 29.36,54.91 28.64,55.63 28.64,55.84 28.79,55.99 29,55.99 29.72,55.27 29.93,55.27 30.08,55.42 30.08,55.63 29.36,56.35 29.36,56.56 29.51,56.71 29.72,56.71 30.44,55.99 30.65,55.99 30.8,56.14 30.8,56.35 30.08,57.07 30.08,57.28 30.23,57.43 30.44,57.43 31.16,56.71 31.37,56.71 31.52,56.86 31.52,57.07 30.8,57.79 30.8,58 30.95,58.15 31.16,58.15 31.88,57.43 32.09,57.43 32.24,57.57 32.24,57.78 31.52,58.51 31.52,58.72 31.66,58.87 31.88,58.87 32.6,58.14 32.81,58.14 32.96,58.29 32.96,58.5 32.23,59.22 32.23,59.43 32.38,59.58 32.59,59.58 33.32,58.86 33.53,58.86 33.67,59.01 33.67,59.22 32.95,59.94 32.95,60.15 33.1,60.3 33.31,60.3 34.03,59.58 34.24,59.58 34.39,59.73 34.39,59.94 33.67,60.66 33.67,60.87 40.68,67.88 48.3,67.88 49.34,68.92 63.44,68.92 70.93,76.41 91.71,76.41 92.01,76.12 v1(92.91,76.12)
  BOTTOM w0.13: v1(92.91,76.12) 93.41,76.62 94.35,76.62 94.66,76.93 94.66,80.82 95.3,81.45 95.3,82.34 95.44,82.49 U99.38
HPA08N: length 127.1
  TOP w0.094: JA1.C10 v4(14.29,47.48)
  L12_SIG w0.102: v4(14.29,47.48) 14.29,47.99 14.65,48.35 18.88,48.35 20.84,50.32 20.84,51.59 28.38,59.13 28.59,59.13 29.23,58.48 29.45,58.48 29.59,58.63 29.59,58.84 28.95,59.48 28.95,59.69 29.1,59.84 29.31,59.84 29.95,59.2 30.16,59.2 30.31,59.35 30.31,59.56 29.67,60.2 29.67,60.41 29.82,60.56 30.03,60.56 30.67,59.92 30.88,59.92 31.03,60.07 31.03,60.28 30.39,60.92 30.39,61.13 30.54,61.28 30.75,61.28 31.39,60.64 31.6,60.64 31.75,60.79 31.75,61 31.11,61.64 31.11,61.85 31.26,62 31.47,62 32.11,61.36 32.32,61.36 32.47,61.5 32.47,61.72 31.82,62.36 31.82,62.57 31.97,62.72 32.18,62.72 32.83,62.07 33.04,62.07 33.19,62.22 33.19,62.43 32.54,63.08 32.54,63.29 32.92,63.67 34.64,63.67 40.1,69.13 45.93,69.13 47.78,70.98 51.75,70.98 52.27,71.51 54.2,71.51 54.31,71.4 59.33,71.4 59.84,70.89 62.91,70.89 69.86,77.83 87.99,77.83 89.15,78.99 89.94,78.99 92.21,81.26 92.21,81.37 93.71,82.86 94.09,82.86 94.36,82.6 97.54,82.6 99.67,80.48 99.67,79.68 v1(101.57,77.77)
  BOTTOM w0.13: R585.1 R571.2 ; R571.2 101.57,79.24 100.38,80.44 100.38,81.33 99.72,81.98 99.01,81.98 98.44,82.55 U99.32 ; R571.2 v1(101.57,77.77)
HPA08P: length 125.9
  TOP w0.094: JA1.C9 v4(14.29,46.85)
  L03_SIG w0.102: v4(14.29,46.85) 14.63,46.5 17.62,46.5 17.7,46.58 19.15,46.58 27.89,55.32 33.27,55.32 34.77,56.82 38.07,56.82 38.79,57.54 40.49,57.54 40.64,57.69 40.64,57.99 40.79,58.14 41,58.14 41.15,57.99 41.15,57.69 41.3,57.54 41.51,57.54 41.66,57.69 41.66,57.99 41.81,58.14 42.02,58.14 42.17,57.99 42.17,57.69 42.32,57.54 48.8,57.54 50.21,58.95 50.21,66.59 52.77,69.16 53.88,69.16 54.03,69.31 54.03,69.67 54.17,69.82 54.39,69.82 54.53,69.67 54.53,69.31 54.68,69.16 65.05,69.16 69.53,73.65 69.53,74.62 70.23,75.32 70.44,75.32 70.76,75 70.97,75 71.12,75.15 71.12,75.36 70.8,75.67 70.8,75.89 70.95,76.03 71.16,76.03 71.48,75.72 71.69,75.72 71.84,75.86 71.84,76.07 71.52,76.39 71.52,76.6 71.66,76.75 71.88,76.75 72.19,76.43 72.4,76.43 72.55,76.58 72.55,76.79 72.23,77.11 72.23,77.32 72.38,77.47 72.59,77.47 72.91,77.15 73.12,77.15 73.27,77.3 73.27,77.51 72.95,77.83 72.95,78.04 73.11,78.2 83,78.2 85.8,81 87.3,81 88.79,79.5 88.79,78.23 91.54,75.48 94.16,75.48 94.27,75.59 99.11,75.59 v1(99.61,75.08)
  BOTTOM w0.13: U99.33 97.94,82.57 98.84,81.67 99.52,81.67 99.61,81.58 R572.2 99.12,80.49 99.12,79.2 R586.1 99.12,78.2 99.12,75.58 v1(99.61,75.08)
HPA09N: length 125.6
  TOP w0.094: JA1.D11 v4(12.65,47.57)
  L12_SIG w0.102: v1(101.52,82.85) 100.8,83.57 99.32,83.57 98.69,82.94 94.5,82.94 94.23,83.2 93.05,83.2 91.79,81.94 87.78,81.94 84.11,78.26 68.26,78.26 66.8,76.81 66.8,75.46 63.69,72.35 59.34,72.35 58.84,71.84 51.71,71.84 51.33,72.23 49.85,72.23 49.36,71.74 48.65,71.74 48.65,71.74 47.54,71.74 46.02,70.22 38.67,70.22 38.21,69.76 38.21,69.55 38.77,68.99 38.77,68.78 38.62,68.63 38.41,68.63 37.85,69.19 37.64,69.19 37.49,69.04 37.49,68.83 38.05,68.27 38.05,68.06 37.9,67.91 37.69,67.91 37.13,68.47 36.92,68.47 36.77,68.32 36.77,68.11 37.33,67.55 37.33,67.34 37.18,67.19 36.97,67.19 36.41,67.75 36.2,67.75 36.05,67.6 36.05,67.39 36.61,66.83 36.61,66.62 36.46,66.47 36.25,66.47 35.69,67.03 35.48,67.03 35.33,66.89 35.33,66.68 35.89,66.11 35.89,65.9 35.74,65.76 35.53,65.76 34.97,66.32 34.76,66.32 34.61,66.17 34.61,65.96 35.17,65.4 35.17,65.19 35.03,65.04 34.81,65.04 34.25,65.6 34.04,65.6 33.9,65.45 33.9,65.24 34.46,64.68 34.46,64.47 34.31,64.32 34.1,64.32 33.54,64.88 33.33,64.88 20.11,51.67 20.11,50.38 19.11,49.37 17.7,49.37 17.16,49.92 14.73,49.92 14.22,49.41 14.22,48.72 13.68,48.18 13.25,48.18 v4(12.65,47.57)
  BOTTOM w0.13: R583.1 102.68,81.81 102.21,82.28 R569.2 101.65,82.72 v1(101.52,82.85) 99.97,84.4 U99.29
